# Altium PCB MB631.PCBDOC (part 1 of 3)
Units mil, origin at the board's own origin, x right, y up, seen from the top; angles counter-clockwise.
Board outline 4505 x 6805 mil, 4 copper layers (TopLayer, GND, VCC, BottomLayer); 273 components, 241 nets, 1286 pads, 636 vias.
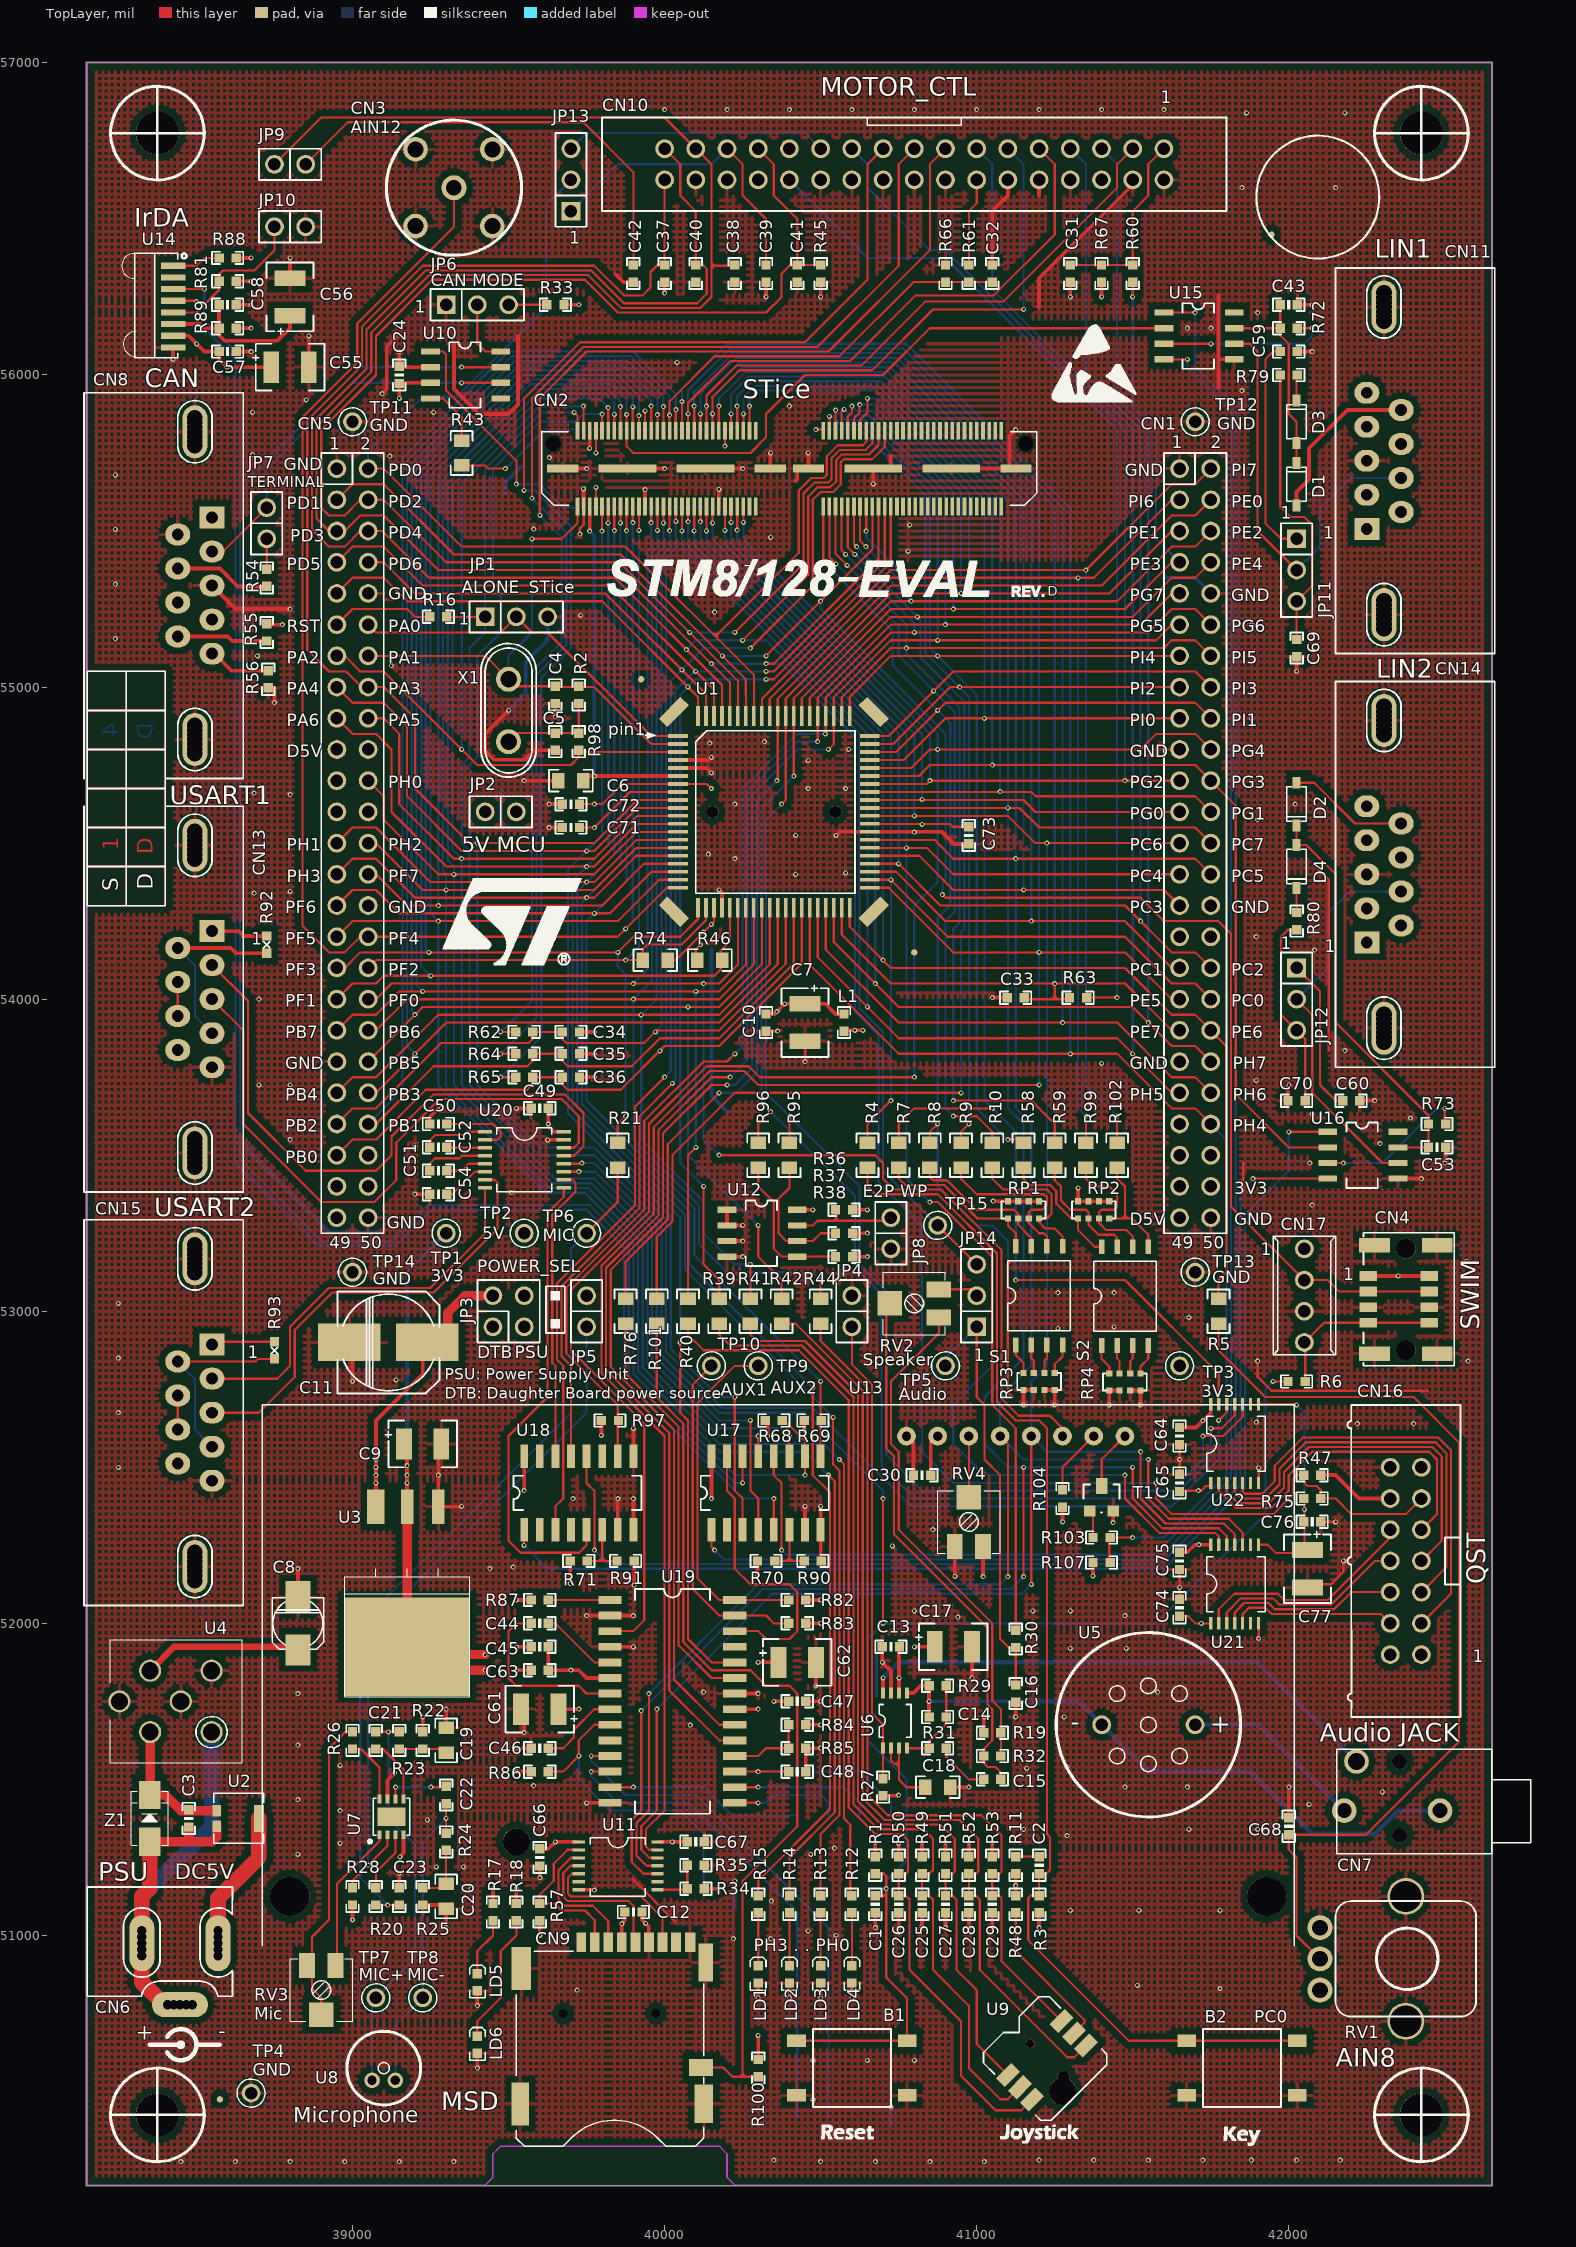
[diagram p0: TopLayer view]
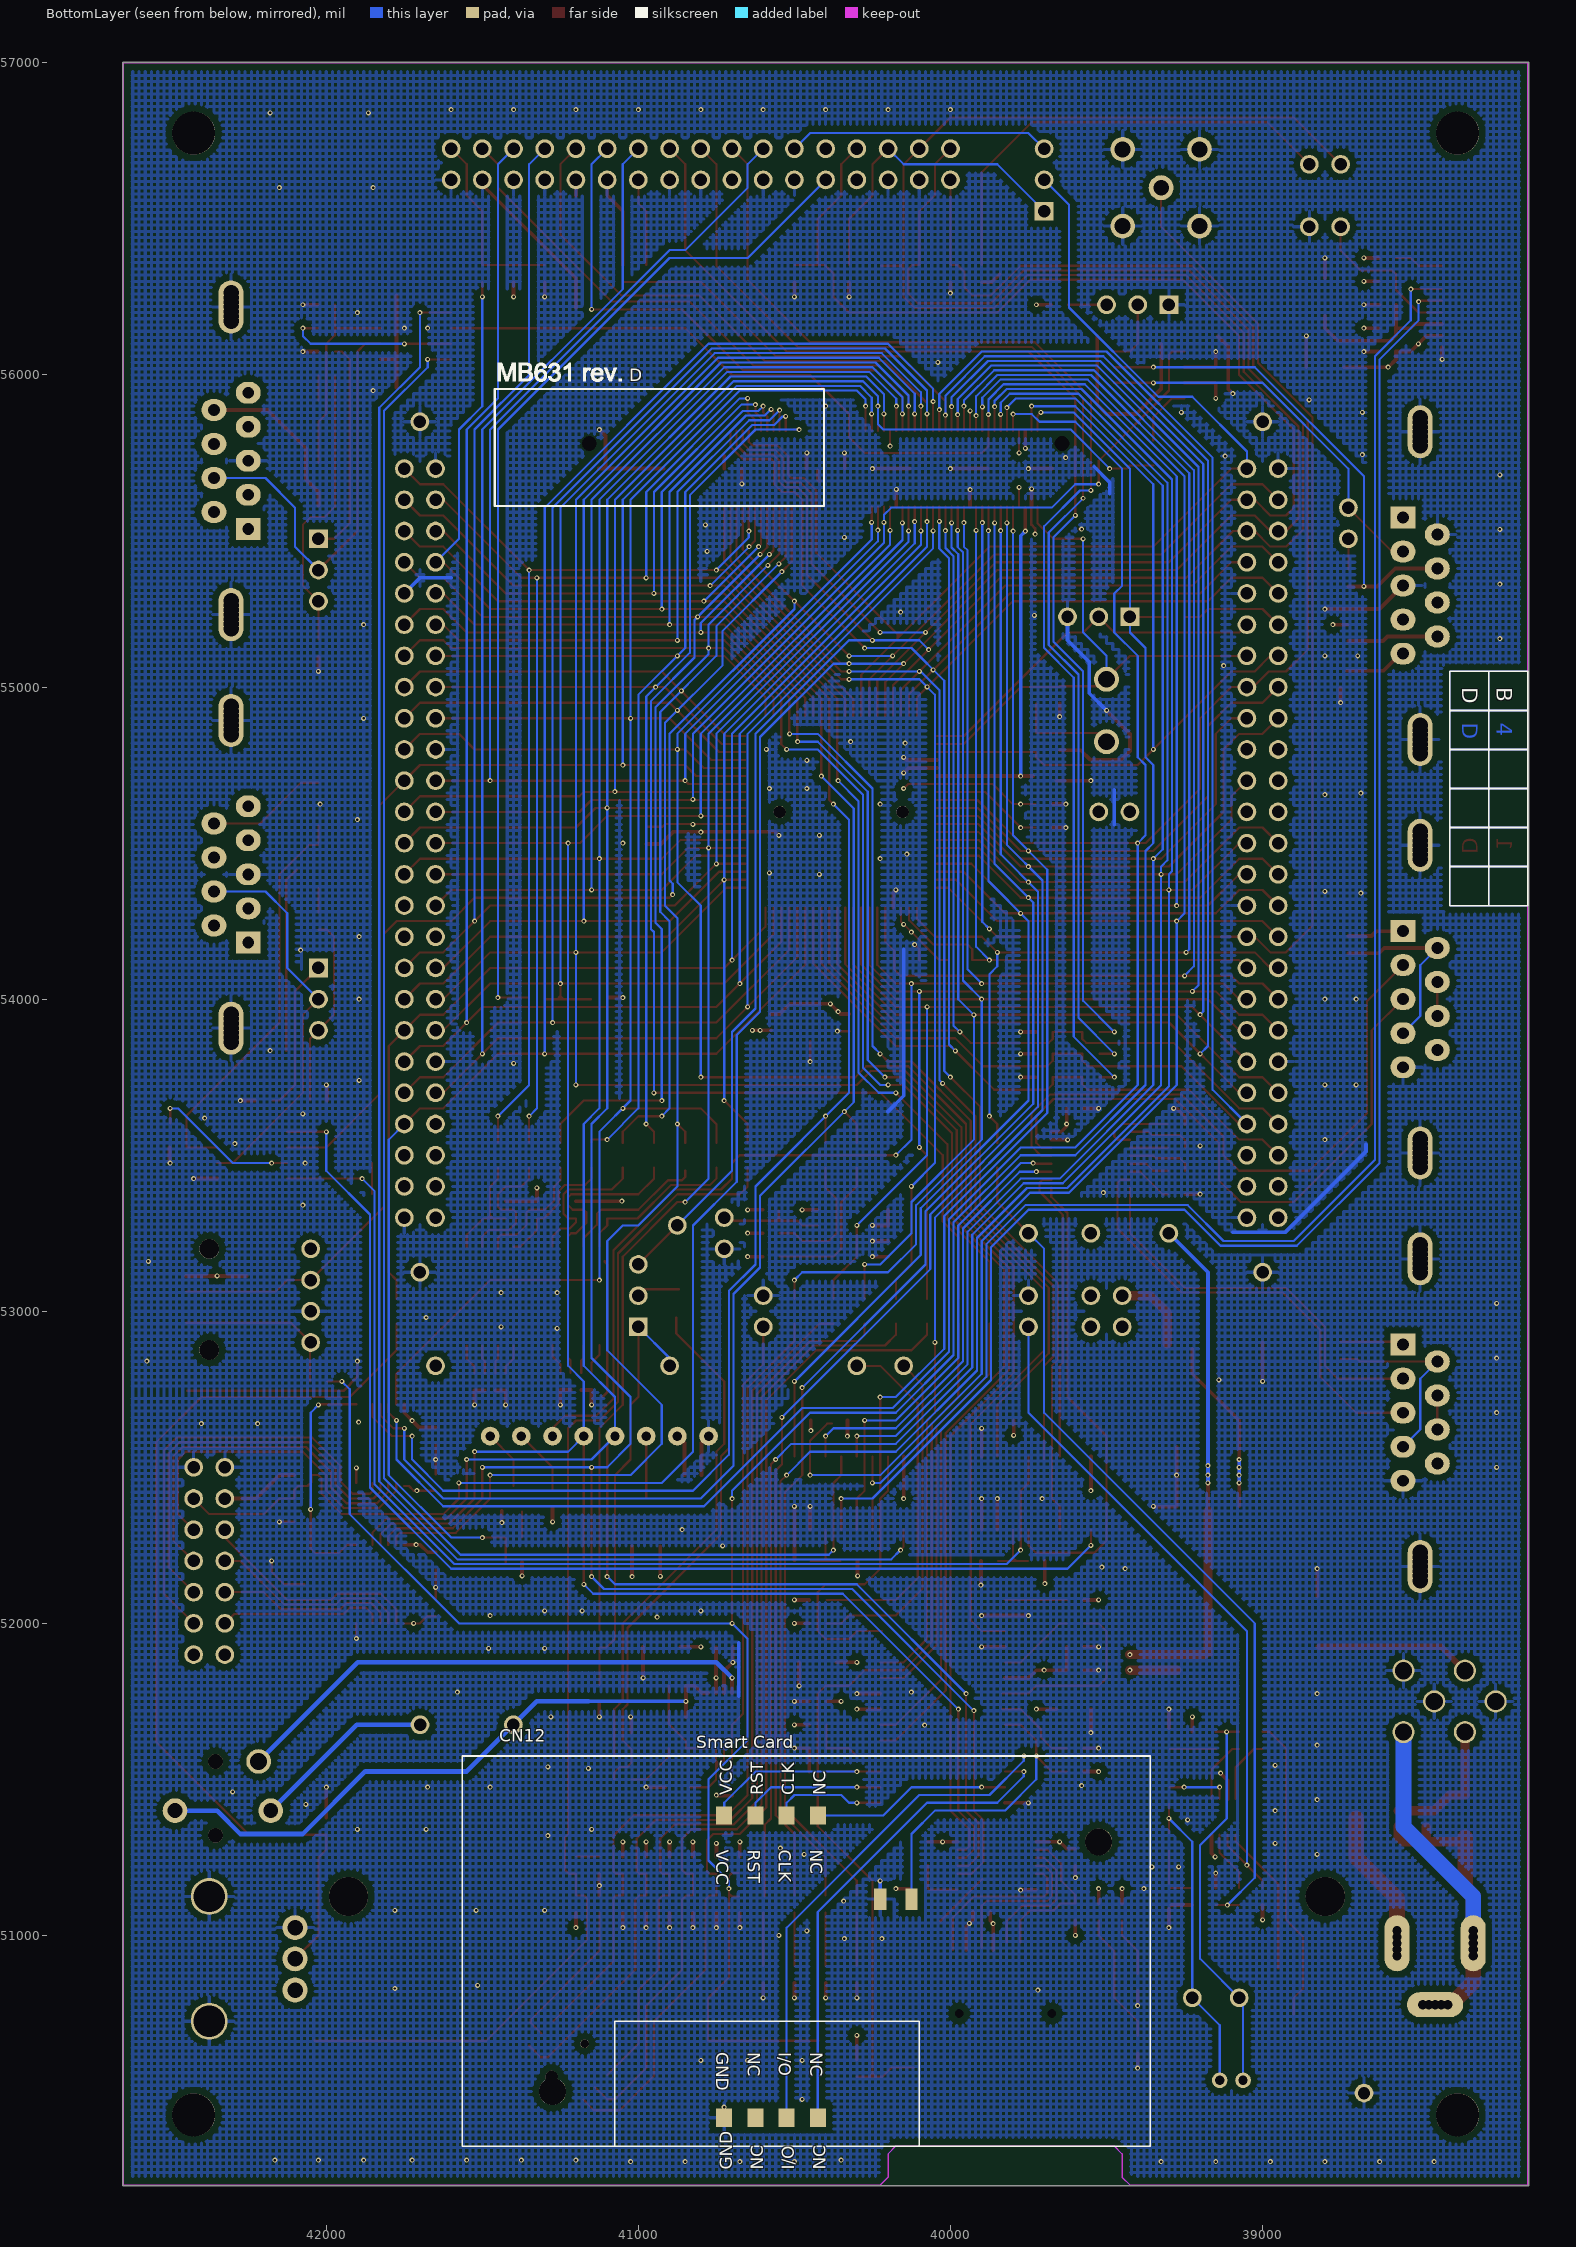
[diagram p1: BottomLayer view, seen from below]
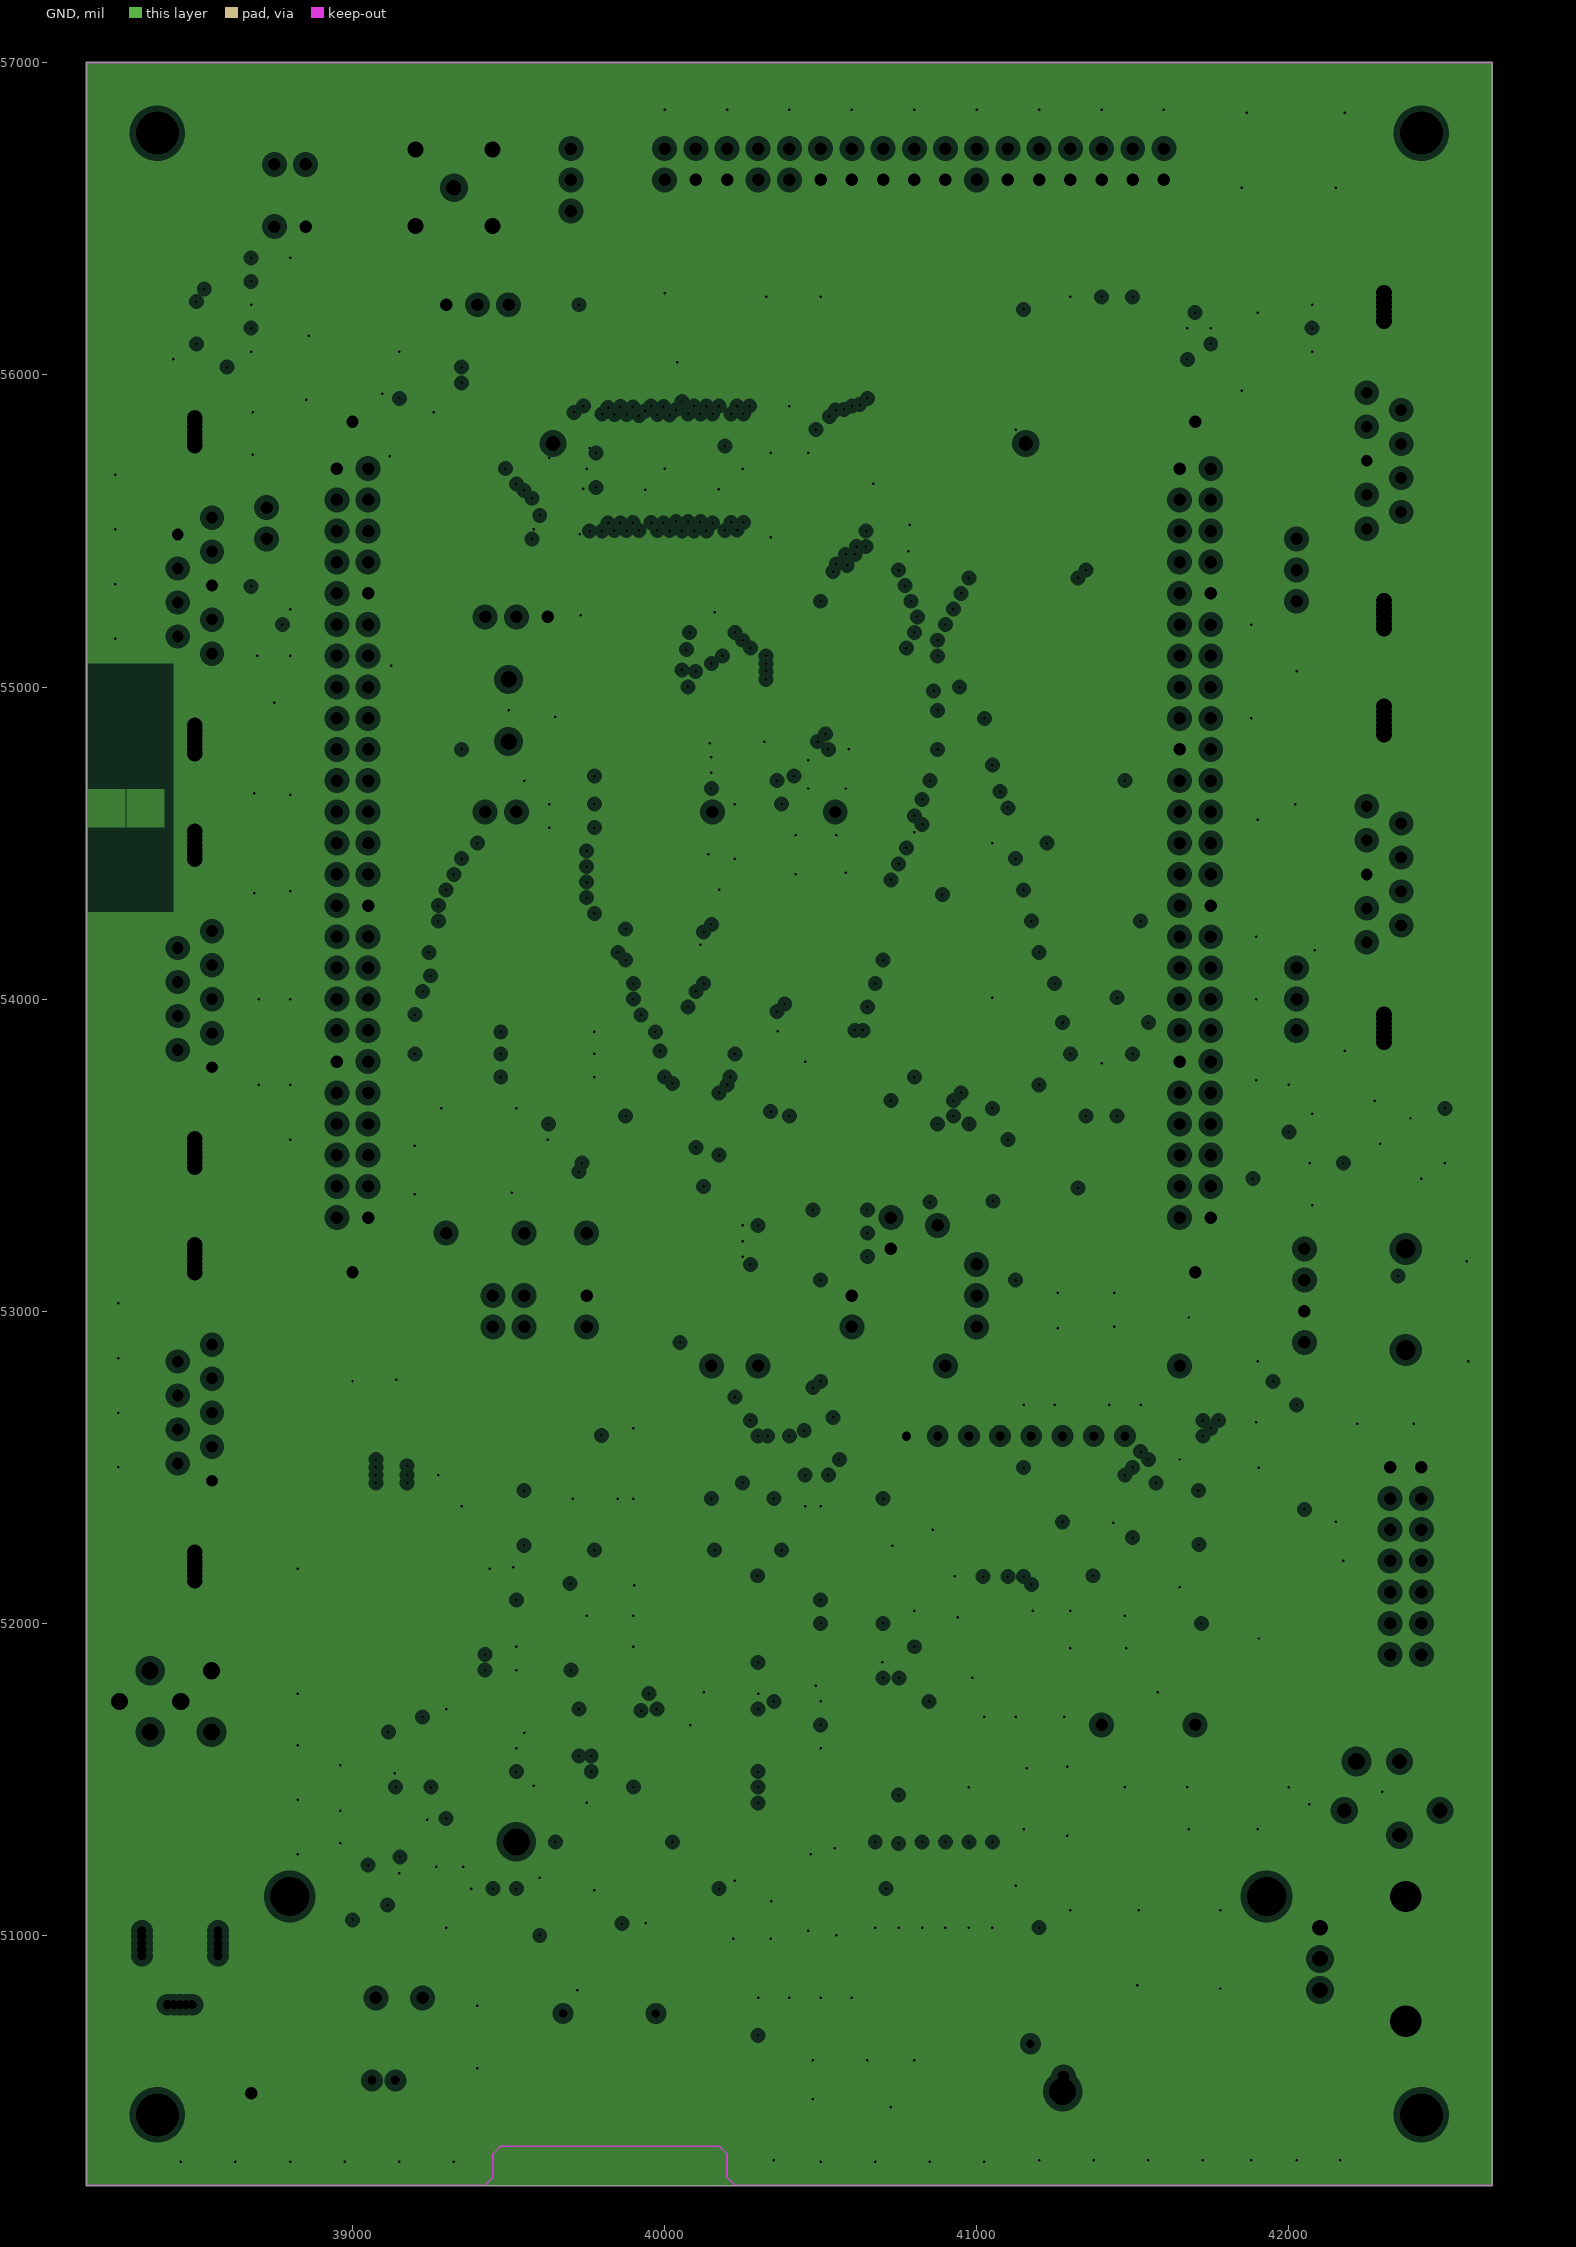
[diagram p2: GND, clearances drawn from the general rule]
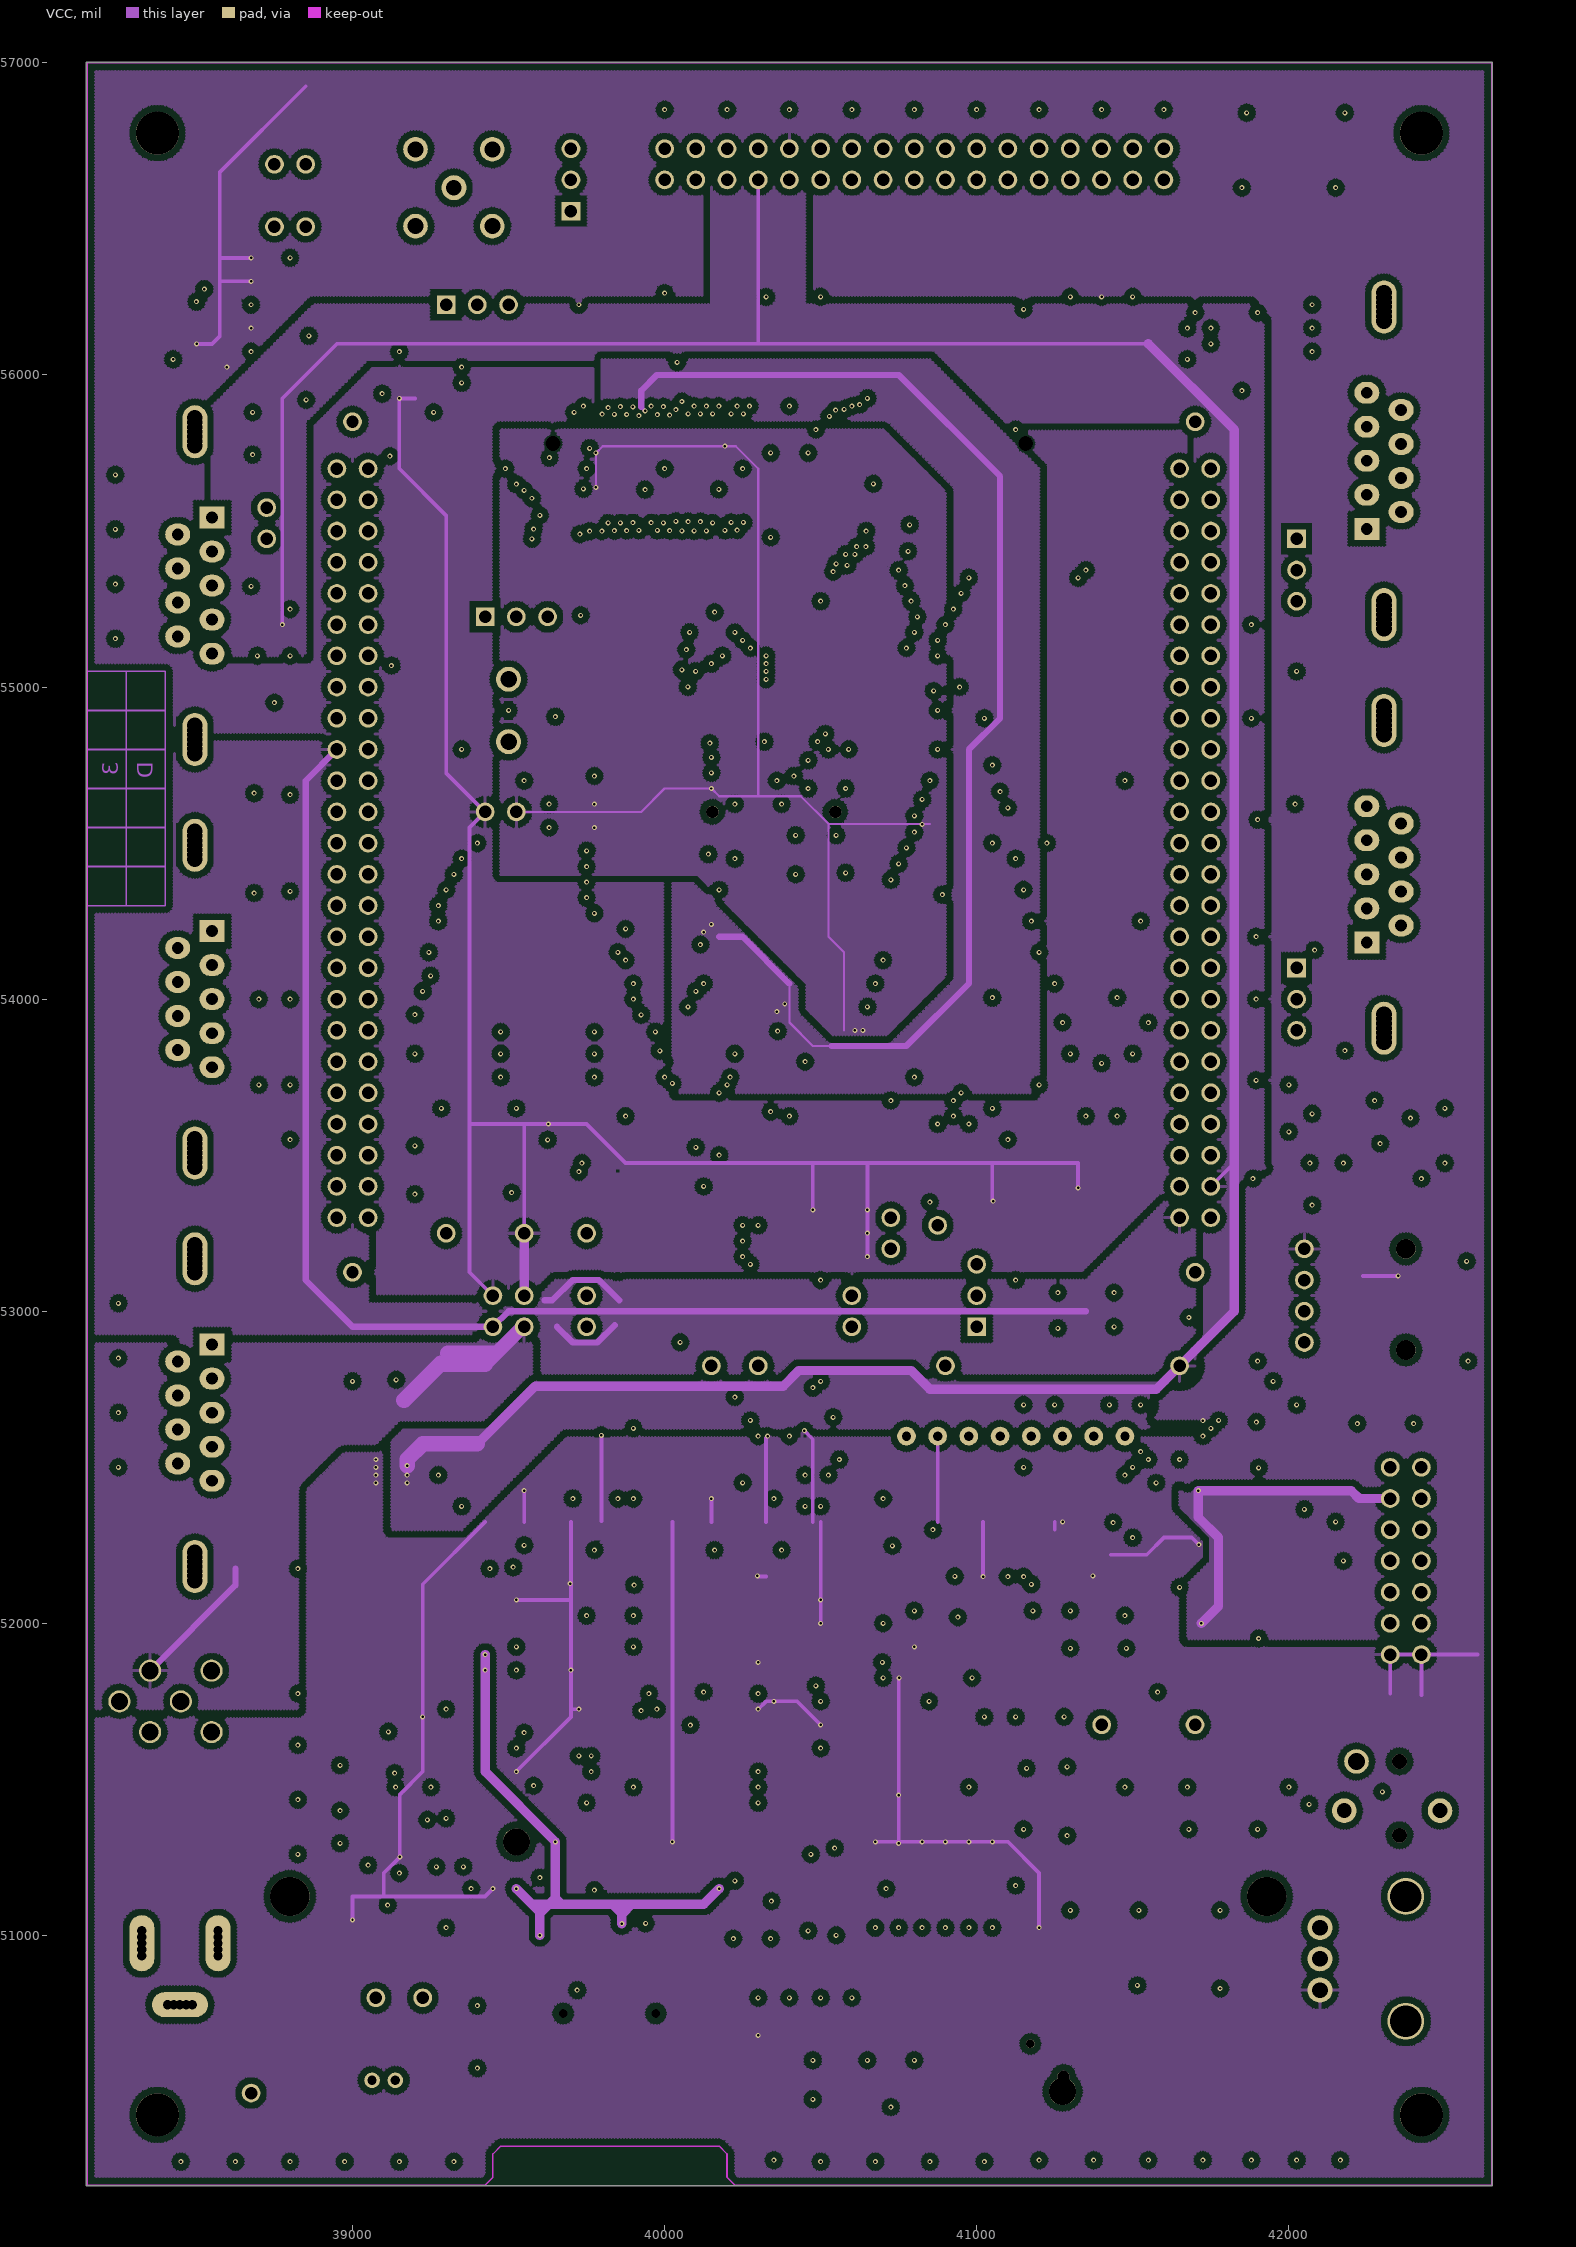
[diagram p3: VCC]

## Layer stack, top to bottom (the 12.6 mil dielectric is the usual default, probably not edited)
TopLayer: signal copper 1.4
Dielectric: core 12.6, FR-4, Dk 4.8
GND: plane copper 1.4, net GND
Dielectric: prepreg 12.6, FR-4, Dk 4.8
VCC: signal copper 1.4
Dielectric: core 12.6, FR-4, Dk 4.8
BottomLayer: signal copper 1.4

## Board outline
38147.5,50197.5 42652.5,50197.5 42652.5,57002.5 38147.5,57002.5

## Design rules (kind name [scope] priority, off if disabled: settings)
Clearance Clearance_2 [InComponent('CN2')] p1: gap=5
Clearance Clearance_1 [(InPoly)] p2: gap=20
Clearance [All] p3: gap=8
ComponentClearance [All] p1 off: gap=10 collisioncheckmode=0
PlaneClearance [All] p1: clearance=20
PlaneConnect [All] p1: planeconnectstyle=Relief reliefexpansion=20 reliefentries=4 reliefconductorwidth=10 reliefairgap=10
PolygonConnect [All] p1: connectstyle=Relief reliefconductorwidth=10 reliefentries=4 polygonreliefangle="90 Angle"
RoutingLayers [All] p1: top layer_v5=TRUE mid layer 1_v5=FALSE bottom layer_v5=TRUE
RoutingVias [All] p1: holewidth=8 width=16 viastyle="Through Hole" minholewidth=5 minwidth=8 maxholewidth=28 maxwidth=50
SolderMaskExpansion [All] p1: expansion=4
TestPointUsage [All] p1: valid=0 allowmultiple=FALSE
Testpoint [All] p1: side=15 testpointundercomponent=TRUE minsize=40 maxsize=100 preferedsize=60 minholesize=20 maxholesize=40 preferedholesize=32 testpointgrid=1 style=1023 order=1234567890
Width Width_3 [InNet('D5V')] p1: maxlimit=300 minlimit=7 preferedwidth=20
Width Width_4 [InNet('E5V')] p2: maxlimit=300 minlimit=7 preferedwidth=50
Width Width_1 [InNet('+3V3')] p3: maxlimit=300 minlimit=7 preferedwidth=30
Width Width_2 [InNet('+5V')] p4: maxlimit=300 minlimit=7 preferedwidth=12
Width Width_7 [InNet('VDD')] p5: maxlimit=300 minlimit=7 preferedwidth=12
Width Width_8 [InNet('VDDA')] p6: maxlimit=300 minlimit=7 preferedwidth=12
Width Width_5 [InNet('GND')] p7: maxlimit=300 minlimit=7 preferedwidth=8
Width Width_6 [InNet('U5V')] p8: maxlimit=300 minlimit=7 preferedwidth=12
Width [All] p9: maxlimit=300 minlimit=5 preferedwidth=7
14 further rules are at their usual default settings.

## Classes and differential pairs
component class JOY_LCD_SDcard_CAN_EEPROM: C24 C25 C26 C27 C28 C29 C30 C66 C67 CN8 CN9 JP6 JP7 JP8 R33 R34 R35 R36 R37 R38 R39 R40 R41 R42 R43 R44 R47 R48 R49 R50 R51 R52 R53 R54 R55 R56 R57 R58 R59 R95 R96 U9 U10 U11 U12 U13
component class UART_LIN_IrDA_SmartCard: B3 B4 C43 C44 C45 C46 C47 C48 C49 C50 C51 C52 C53 C54 C55 C56 C57 C58 C59 C60 C61 C62 C63 CN11 CN12 CN13 CN14 CN15 D1 D2 JP10 JP11 JP12 R68 R69 R70 R71 R72 R73 R76 R78 R79 R80 R81 R82 R83 R84 R85 R86 R87 R88 R89 R90 R91 R92 R93 R94 R97 TP9 TP10 U14 U15 U16 U17 U18 U19 U20
net class PE[0..15]: NetCN13_7 NetR92_1 PE0 PE1 PE2 PE3 PE6 PE7 PE8 PE9 PE10 PE11 PE12 PE13 PE14 PE15 PE[0..15]0 PE[0..15]1 PE[0..15]2 PE[0..15]3 PE[0..15]4 PE[0..15]5 PE[0..15]6 PE[0..15]7 PE[0..15]8 PE[0..15]9 PE[0..15]10 PE[0..15]11 PE[0..15]12 PE[0..15]13 PE[0..15]14 PE[0..15]15
net class PD[0..15]: NetJP13_3 PD0 PD1 PD2 PD3 PD4 PD5 PD6 PD7 PD8 PD9 PD10 PD11 PD12 PD14 PD15 PD[0..15]0 PD[0..15]1 PD[0..15]2 PD[0..15]3 PD[0..15]4 PD[0..15]5 PD[0..15]6 PD[0..15]7 PD[0..15]8 PD[0..15]9 PD[0..15]10 PD[0..15]11 PD[0..15]12 PD[0..15]13 PD[0..15]14 PD[0..15]15
net class PC[0..15]: NetCN12_2 NetCN12_3 NetU19_13 PC3 PC4 PC5 PC6 PC7 PC8 PC9 PC10 PC11 PC12 PC13 PC14 PC15 PC[0..15]0 PC[0..15]1 PC[0..15]2 PC[0..15]3 PC[0..15]4 PC[0..15]5 PC[0..15]6 PC[0..15]7 PC[0..15]8 PC[0..15]9 PC[0..15]10 PC[0..15]11 PC[0..15]12 PC[0..15]13 PC[0..15]14 PC[0..15]15
net class PB[0..15]: PB0 PB1 PB2 PB3 PB4 PB5 PB6 PB7 PB8 PB9 PB10 PB11 PB12 PB13 PB14 PB15 PB[0..15]0 PB[0..15]1 PB[0..15]2 PB[0..15]3 PB[0..15]4 PB[0..15]5 PB[0..15]6 PB[0..15]7 PB[0..15]8 PB[0..15]9 PB[0..15]10 PB[0..15]11 PB[0..15]12 PB[0..15]13 PB[0..15]14 PB[0..15]15
net class PA[0..15]: NetU19_11 NetU19_12 PA0 PA3 PA4 PA5 PA6 PA7 PA8 PA9 PA10 PA11 PA12 PA13 PA14 PA15 PA[0..15]0 PA[0..15]1 PA[0..15]2 PA[0..15]3 PA[0..15]4 PA[0..15]5 PA[0..15]6 PA[0..15]7 PA[0..15]8 PA[0..15]9 PA[0..15]10 PA[0..15]11 PA[0..15]12 PA[0..15]13 PA[0..15]14 PA[0..15]15
component class Extension: CN12 CN13 R59 R60
component class JTAG&SWD: CN7 CN9 CN10 JP10 R101 R102 R103 R104 R105 R109 R110 R111 R122 R124 R125 R129 R130
component class MotorCtrl: C48 C49 C50 C51 C52 C53 C71 C72 C73 C74 C75 C76 CN10 JP8 JP12 R20 R53 R54 R55 R56 R57 R58 R61
component class MCU: B1 BT1 C1 C2 C3 C4 C5 C55 C56 C57 C58 C59 C60 C61 JP9 L1 R1 R2 R15 R26 R83 R84 R86 R87 SW1 SW2 TP8 U1 X1 X2
component class Peripherals: C6 C7 C8 C9 C10 CN1 CN2 CN3 JP1 JP2 JP3 LD1 LD2 LD3 LD4 R3 R4 R5 R6 R7 R8 R9 R11 R12 R13 R14 R16 R17 R18 R19 R20 R21 R63 R65 R66 R67 R68 R69 R80 R88 R89 R90 R91 R112 R113 R114 R116 R118 RV1 T1 T2 TR1 TR2 U2 U3 U4 U5
component class Power: C11 C12 C13 C14 C15 CN4 JP4 LD5 R22 TP1 TP2 TP3 U6 U7 U8 Z1
component class RS232&IrDA: C16 C17 C18 C19 C20 C21 C22 C23 C24 C25 C26 C27 C28 C29 CN5 CN6 JP5 R23 R24 R25 R27 R28 R64 R70 R77 R79 U9 U10 U11
component class Audio: C30 C31 C32 C33 C34 C35 C36 C37 C38 C39 C54 CN8 JP6 JP7 R29 R30 R31 R32 R33 R34 R35 R36 R37 R38 R39 R40 R71 R119 RV2 RV3 TP4 TP5 TP6 TP7 U12 U13 U14 U15
component class LCD&Joystick: B1 B2 B3 C40 C41 C42 C43 C44 C45 C46 C47 C70 R41 R42 R43 R44 R45 R46 R47 R48 R49 R50 R51 R52 R62 R72 R73 R74 R75 R76 R78 R85 R92 R93 R106 R107 R108 R120 R121 U16 U17 U19
component class MC&Extension: C48 C49 C50 C51 C52 C53 C71 C72 C73 C74 C75 CN10 CN12 CN13 JP8 R53 R54 R55 R56 R57 R58 R59 R60 R61
component class SD&SmartCard: C62 C63 C64 C65 C66 C67 C68 C69 CN15 CN16 R81 R82 R94 R95 R96 R97 R98 R99 R100 R115 R117 TP9 TP10 U18
component class Debug: CN7 CN9 CN10 CN11 JP10 R101 R102 R103 R104 R105 R109 R110 R111

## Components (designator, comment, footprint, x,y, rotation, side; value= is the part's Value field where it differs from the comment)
B1 "RESET" PB10 40600,50575 r90 top
B2 "USER" PB10 41850,50575 r90 top
C1 "100nF" 0603P 40675,51100 r90 top
C2 "100nF" 0603P 41200,51225 r270 top
C3 "100nF" 0603P 38475,51375 r270 top
C4 "20pF" 0603 39650,54975 r270 top
C5 "20pF" 0603 39650,54825 r270 top
C6 "470nF" 0805 39700,54700 r270 top
C7 "10uF" TAN-B 40450,53925 r270 top
C8 "10uF" C160M 38825,52000 r270 top
C9 "10uF" TAN-B 39225,52575 r0 top
C10 "10nF" 0603 40325,53925 r270 top
C11 "470uF" C310M 39115,52900 r0 top
C12 "100nF" 0603P 39900,51075 r0 top
C13 "100nF" 0603P 40725,51925 r0 top
C14 "470pF" 0603 40875,51700 r180 top
C15 "150nF" 0603 41050,51500 r180 top
C16 "33nF" 0603 41125,51775 r90 top
C17 "100uF" TAN-B 40925,51925 r0 top
C18 "2.2uF" 0805 40875,51475 r90 top
C19 "2.2uF" 0805 39300,51625 r180 top
C20 "2.2uF" 0805 39300,51125 r0 top
C21 "1uF" 0603 39075,51625 r270 top
C22 "1uF" 0603 39300,51450 r90 top
C23 "do not fit" 0603 39150,51125 r90 top
C24 "100nF" 0603P 39150,56000 r270 top
C25 "100nF" 0603P 40825,51100 r90 top
C26 "100nF" 0603P 40750,51100 r90 top
C27 "100nF" 0603P 40900,51100 r90 top
C28 "100nF" 0603P 40975,51100 r90 top
C29 "100nF" 0603P 41050,51100 r90 top
C30 "100nF" 0603P 40825,52475 r180 top
C31 "1nF" 0603 41300,56325 r90 top
C32 "100nF" 0603 41050,56325 r270 top
C33 "100nF" 0603 41125,54005 r0 top
C34 "do not fit" 0603 39700,53895 r180 top
C35 "do not fit" 0603 39700,53825 r180 top
C36 "do not fit" 0603 39700,53750 r180 top
C37 "do not fit" 0603 40000,56325 r90 top
C38 "do not fit" 0603 40225,56325 r90 top
C39 "do not fit" 0603 40325,56325 r90 top
C40 "do not fit" 0603 40100,56325 r90 top
C41 "do not fit" 0603 40425,56325 r90 top
C42 "10nF" 0603 39900,56325 r90 top
C43 "100nF" 0603P 42000,56225 r0 top
C44 "100nF" 0603P 39600,52000 r0 top
C45 "100nF" 0603P 39600,51925 r180 top
C46 "100nF" 0603P 39600,51600 r180 top
C47 "100nF" 0603P 40425,51750 r0 top
C48 "100nF" 0603P 40425,51525 r180 top
C49 "100nF" 0603P 39600,53650 r180 top
C50 "0.33uF" 0603P 39275,53600 r0 top
C51 "0.33uF" 0603P 39275,53450 r0 top
C52 "0.47uF" 0603P 39275,53525 r0 top
C53 "100nF" 0603P 42475,53525 r0 top
C54 "0.33uF" 0603P 39275,53375 r0 top
C55 "4.7uF" TAN-B 38800,56025 r0 top
C56 "4.7uF" TAN-B 38800,56250 r90 top
C57 "0.1uF" 0603P 38600,56075 r0 top
C58 "0.1uF" 0603P 38600,56225 r0 top
C59 "220pF" 0603 42000,56075 r180 top
C60 "220pF" 0603 42200,53675 r180 top
C61 "47uF" TAN-B 39600,51725 r180 top
C62 "47uF" TAN-B 40425,51875 r0 top
C63 "330nF" 0603 39600,51850 r180 top
C64 "100nF" 0603P 41650,52600 r90 top
C65 "100nF" 0603P 41650,52450 r270 top
C66 "100nF" 0603P 39600,51250 r90 top
C67 "100nF" 0603P 40100,51300 r180 top
C68 "100nF" 0603p 42000,51350 r90 top
C69 "1nF" 0603 42025,55125 r90 top
C70 "1nF" 0603 42025,53675 r0 top
C71 "100nF" 0603P 39700,54550 r180 top
C72 "100nF" 0603P 39700,54625 r180 top
C73 "100nF" 0603P 40975,54525 r270 top
C74 "100nF" 0603P 41650,52050 r270 top
C75 "100nF" 0603P 41650,52200 r90 top
C76 "100nF" 0603P 42075,52325 r180 top
C77 "10uF(do not fit)" TAN-B 42060,52175 r270 top
CN1 "Header 25X2 on the left" 2*25P 41650,55700 r0 top locked
CN2 "QTH-060-01-L-D-A" QTH-060-01-L-D-A 40400,55700 r0 top
CN3 "VB334" VB334 39325,56600 r0 top
CN4 "214017" SMD214012 42375,53200 r270 top
CN5 "Header 25X2 on the right" 2*25P 38950,55700 r0 top locked
CN6 "DC-10B" DC10B 38325,50975 r0 top
CN7 "ST-613" PJST-613 42650,51400 r180 top
CN8 "DB9-male CAN connector" DB9/M 38550,55325 r90 top
CN9 "PJS008-2000" MSD(PJS008) 39675,50750 r270 top
CN10 "MC_connector" IDC34S 41600,56725 r270 top locked
CN11 "DB9-male LIN1" DB9/M 42250,55725 r270 top
CN12 "C816" SAM(C816) 40400,50900 r270 bottom
CN13 "DB9-male USART1" DB9/M 38550,54000 r90 top
CN14 "DB9-male LIN2" DB9/M 42250,54400 r270 top
CN15 "DB9-male USART2" DB9/M 38550,52675 r90 top
CN16 "QST(HE10x14)" IDC14S 42425,51900 r180 top
CN17 "609-1306-ND(do not fit)" 609-1306-ND 42050,53200 r270 top
D1 "BAT48ZFILM" SOD-123 42025,55650 r90 top
D2 "BAT48ZFILM" SOD-123 42025,54625 r270 top
D3 "BAT48ZFILM" SOD-123 42025,55850 r90 top
D4 "BAT48ZFILM" SOD-123 42025,54425 r270 top
JP1 "" SIP3 39425,55225 r0 top
JP2 "" SIP2 39525,54600 r180 top
JP3 "Header 2X2H" 2*2P 39450,52950 r0 top
JP4 "" SIP2 40600,52950 r90 top
JP5 "" SIP2 39750,52950 r90 top
JP6 "" SIP3 39300,56225 r0 top
JP7 "" SIP2 38725,55475 r90 top
JP8 "" SIP2 40725,53300 r270 top
JP9 "" SIP2 38750,56675 r0 top
JP10 "" SIP2 38750,56475 r0 top
JP11 "" SIP3 42025,55475 r270 top
JP12 "" SIP3 42025,54100 r270 top
JP13 "" SIP3 39700,56525 r90 top
JP14 "" SIP3 41000,52950 r90 top
L1 "BEAD" 0603 40575,53925 r90 top
LD1 "red" D0603 40300,50875 r0 top
LD2 "red" D0603 40400,50875 r0 top
LD3 "red" D0603 40500,50875 r0 top
LD4 "red" D0603 40600,50875 r0 top
LD5 "red" D0603 39400,50850 r0 top
LD6 "red" D0603 39400,50650 r0 top
R1 "10K" 0603 40675,51225 r90 top
R2 "1M" 0603 39725,54975 r90 top
R3 "4K7" 0603 41200,51100 r270 top
R4 "0" 0805 40650,53500 r0 top
R5 "0" 0805 41775,53000 r0 top
R6 "0" 0603 42025,52775 r0 top
R7 "0" 0805 40750,53500 r180 top
R8 "0" 0805 40850,53500 r180 top
R9 "0" 0805 40950,53500 r180 top
R10 "0" 0805 41050,53500 r180 top
R11 "100" 0603 41125,51225 r90 top
R12 "1K" 0603 40600,51100 r90 top
R13 "1K" 0603 40500,51100 r90 top
R14 "1K" 0603 40400,51100 r90 top
R15 "1K" 0603 40300,51100 r90 top
R16 "820" 0603 39275,55225 r0 top
R17 "300" 0603 39450,51075 r90 top
R18 "300" 0603 39525,51075 r90 top
R19 "0" 0603 41050,51650 r0 top
R20 "0" 0603 39075,51125 r90 top
R21 "0" 0805 39850,53500 r0 top
R22 "1K" 0603 39225,51625 r90 top
R23 "1K" 0603 39150,51625 r90 top
R24 "1K" 0603 39300,51300 r90 top
R25 "1K" 0603 39225,51125 r90 top
R26 "1K" 0603 39000,51625 r270 top
R27 "10K" 0603 40700,51475 r270 top
R28 "10K" 0603 39000,51125 r90 top
R29 "100K" 0603 40875,51800 r180 top
R30 "1.2K" 0603 41125,51950 r270 top
R31 "22K" 0603 40875,51600 r180 top
R32 "0(don't solder)" 0603 41050,51575 r180 top
R33 "10K" 0603 39650,56225 r0 top
R34 "0" 0603 40100,51150 r0 top
R35 "do not fit" 0603 40100,51225 r180 top
R36 "10K" 0603 40575,53325 r180 top
R37 "4K7" 0603 40575,53250 r180 top
R38 "4K7" 0603 40575,53175 r180 top
R39 "0" 0805 40175,53000 r180 top
R40 "0" 0805 40075,53000 r180 top
R41 "0" 0805 40275,53000 r180 top
R42 "0" 0805 40375,53000 r180 top
R43 "0" 0805 39350,55750 r0 top
R44 "0" 0805 40500,53000 r180 top
R45 "10K" 0603 40500,56325 r90 top
R46 "0" 0805 40145,54125 r90 top
R47 "do not fit" 0603 42075,52475 r0 top
R48 "100" 0603 41125,51100 r270 top
R49 "10K" 0603 40825,51225 r270 top
R50 "10K" 0603 40750,51225 r90 top
R51 "10K" 0603 40900,51225 r90 top
R52 "10K" 0603 40975,51225 r90 top
R53 "10K" 0603 41050,51225 r90 top
R54 "120" 0603 38725,55350 r90 top
R55 "do not fit" 0603 38725,55175 r270 top
R56 "0" 0603 38730,55025 r90 top
R57 "4K7" 0603 39600,51075 r270 top
R58 "0" 0805 41150,53500 r180 top
R59 "0" 0805 41250,53500 r180 top
R60 "0" 0603 41500,56325 r270 top
R61 "0" 0603 40975,56325 r270 top
R62 "0" 0603 39550,53895 r180 top
R63 "0" 0603 41325,54005 r180 top
R64 "0" 0603 39550,53825 r180 top
R65 "0" 0603 39550,53750 r180 top
R66 "100K" 0603 40900,56325 r270 top
R67 "3.3K" 0603 41400,56325 r270 top
R68 "10K" 0603 40350,52650 r0 top
R69 "10K" 0603 40475,52650 r0 top
R70 "10K" 0603 40325,52200 r0 top
R71 "10K" 0603 39725,52200 r0 top
R72 "4K7" 0603 42000,56150 r180 top
R73 "4K7" 0603 42475,53600 r180 top
R74 "0" 0805 39970,54125 r90 top
R75 "50K" 0603 42075,52400 r0 top
R76 "0" 0805 39875,53000 r0 top
R79 "1K" 0603 42000,56000 r180 top
R80 "1K" 0603 42025,54250 r270 top
R81 "10K" 0603 38600,56300 r0 top
R82 "10K" 0603 40425,52075 r180 top
R83 "10K" 0603 40425,52000 r180 top
R84 "10K" 0603 40425,51675 r180 top
R85 "10K" 0603 40425,51600 r0 top
R86 "100K" 0603 39600,51525 r0 top
R87 "4K7" 0603 39600,52075 r0 top
R88 "5" 0603 38600,56375 r180 top
R89 "47" 0603 38600,56150 r180 top
R90 "0" 0603 40475,52200 r0 top
R91 "0" 0603 39875,52200 r180 top
R92 "do not fit" 0603_NC 38725,54175 r90 top
R93 "do not fit" 0603_NC 38750,52875 r90 top
R95 "0" 0805 40400,53500 r0 top
R96 "0" 0805 40300,53500 r0 top
R97 "10K" 0603 39825,52650 r0 top
R98 "60" 0603 39725,54825 r90 top
R99 "0" 0805 41350,53500 r180 top
R100 "10K" 0603 40300,50575 r90 top
R101 "0" 0805 39975,53000 r180 top
R102 "0" 0805 41450,53500 r180 top
R103 "1K" 0603 41400,52275 r0 top
R104 "0" 0603 41275,52400 r90 top
R107 "do not fit" 0603 41400,52195 r0 top
RP1 "10K" RES-4B 41150,53325 r0 top
RP2 "10K" RES-4B 41375,53325 r0 top
RP3 "50" RES-4B 41200,52775 r0 top
RP4 "50" RES-4B 41475,52773.27 r0 top
RV1 "10K" ADJRH 42100,50925 r270 top
RV2 "50K" 3314-J 40800,53025 r270 top
RV3 "20K" 3314-J 38900,50825 r0 top
RV4 "50K(do not fit)" 3314-J 40975,52325 r180 top
S1 "SW" GWL4 41200,53050 r90 top
S2 "SW" GWL4 41475,53048.27 r90 top
T1 "9013" SOT-23 41400,52400 r0 top
TP1 "3V3" TP 39300,53250 r0 top
TP2 "+5V" TP 39550,53250 r270 top
TP3 "+3V3" TP 41650,52825 r270 top
TP4 "Ground" TP 38675,50495 r270 top
TP5 "Audio" TP 40900,52825 r90 top
TP6 "MIC_OUT" TP 39750,53250 r0 top
TP7 "MIC+" TP 39075,50800 r0 top
TP8 "MIC-" TP 39225,50800 r0 top
TP9 "AUX2" TP 40300,52825 r0 top
TP10 "AUX1" TP 40150,52825 r0 top
TP11 "GND" TP 39000,55850 r0 top
TP12 "GND" TP 41700,55850 r0 top
TP13 "GND" TP 41700,53125 r0 top
TP14 "GND" TP 39000,53125 r0 top
TP15 "BEEP" TP 40875,53275 r0 top
U1 "STM8S2XX" LQFP80 40350,54600 r0 top
U2 "ZEN056V130A24LS" polyzen 38700,51375 r180 top
U3 "LD1086D2M33" D2PAK/A 39175,51925 r90 top
U4 "BNX002-01" BNX001 38450,51750 r180 top
U5 "KDMG15008-03" KS1508 41550,51675 r180 top
U6 "TS4871IST" TSSOP8 40700,51600 r90 top
U7 "MAX4061ETA+T" QFNT8 39125,51380 r90 top
U8 "KECG2740TBL" KEC2740 39100,50575 r90 top
U9 "MT008-A" JOY 41225,50600 r45 top
U10 "L9616D" SO8 39250,56075 r270 top
U11 "MAX3378EEUD" TSSOP14 39725,51300 r0 top
U12 "M24C64-WMN6" SO8 40200,53325 r270 top
U13 "HXM122032-GB1 (5V)" LCD12232-GB1 40775,52600 r0 top locked
U14 "TFDU4300" IR_VISHAY3 38425,56350 r180 top
U15 "L9638D" SO8 41600,56200 r270 top
U16 "L9638D" SO8 42125,53575 r270 top
U17 "M74HC4052M1R" SO16 40150,52300 r0 top
U18 "M74HC4052M1R" SO16 39550,52300 r0 top
U19 "ST8024CDR" SO28 39825,52075 r0 top
U20 "ST3232ECTR" TSSOP16 39425,53575 r0 top
U21 "MAX3378EEUD" TSSOP14 41750,52000 r90 top
U22 "MAX3378EEUD" TSSOP14 41750,52450 r90 top
X1 "24MHz (with socket)" XTAL_socket 39500,54925 r270 top
Z1 "SMAJ5.0A-TR" 1R1C 38350,51375 r0 top

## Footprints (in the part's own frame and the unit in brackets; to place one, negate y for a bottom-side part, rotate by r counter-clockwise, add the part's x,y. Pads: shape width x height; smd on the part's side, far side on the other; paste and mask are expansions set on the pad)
1R1C [mm]
  rect 1.75x2.3 smd: 1(0,-1.9) 2(0,1.9)
  silkscreen extent -1.5,-2.2 1.5,2.2
2*2P [mil]
  round 60 hole 40: 1(0,0) 2(0,100) 3(100,0) 4(100,100)
  silkscreen extent -50,-50 150,150
2*25P [mil]
  round 60 hole 40: 1(0,0) 2(100,0) 3(0,-100) 4(100,-100) 5(0,-200) 6(100,-200) 7(0,-300) 8(100,-300) 9(0,-400) 10(100,-400) 11(0,-500) 12(100,-500) 13(0,-600) 14(100,-600) 15(0,-700) 16(100,-700) 17(0,-800) 18(100,-800) 19(0,-900) 20(100,-900) 21(0,-1000) 22(100,-1000) 23(0,-1100) 24(100,-1100) 25(0,-1200) 26(100,-1200) 27(0,-1300) 28(100,-1300) 29(0,-1400) 30(100,-1400) 31(0,-1500) 32(100,-1500) 33(0,-1600) 34(100,-1600) 35(0,-1700) 36(100,-1700) 37(0,-1800) 38(100,-1800) 39(0,-1900) 40(100,-1900) 41(0,-2000) 42(100,-2000) 43(0,-2100) 44(100,-2100) 45(0,-2200) 46(100,-2200) 47(0,-2300) 48(100,-2300) 49(0,-2400) 50(100,-2400)
  silkscreen extent -50,-2450 150,50
0603 [mil]
  rect 30x30 smd: 1(-27.5,0) 2(27.5,0)
  silkscreen extent -50,-20 50,20
0603_NC [mil]
  rect 30x30 smd: 1(-27.5,0) 2(27.5,0)
  silkscreen extent -11,-10 9,10
0603P [mil]
  rect 30x30 smd: 1(-27.5,0) 2(27.5,0)
  silkscreen extent -50,-20 50,20
0603p [mil]
  rect 30x30 smd: 1(-27.5,0) 2(27.5,0)
  silkscreen extent -50,-20 50,20
609-1306-ND [mil]
  round 60 hole 40: 1(0,0) 2(100,0) 3(200,0) 4(300,0)
  silkscreen extent -40,-100 340,100
0805 [mil]
  rect 50x40 smd: 1(0,40) 2(0,-40)
  silkscreen extent -35,-70 35,70
3314-J [mm]
  rect 1.3x2 smd: 1(-1.15,2) 3(1.15,2)
  rect 2x2 smd: 2(0,-2)
  silkscreen extent -2.54,-2.54 2.54,2.54
ADJRH [mil]
  round 118.11 hole 100: 0(-200,275) 0(200,275)
  round 80 hole 50: 1(-100,0) 2(0,0) 3(100,0)
  silkscreen extent -185,50 185,500
BNX001 [mm]
  round 1.8 hole 1.4: 1(2.5,2.5) 2(-2.5,2.5) 3(2.5,-2.5) 4(0,0) 5(5,0) 6(-2.5,-2.5)
  silkscreen extent -5,-5 5.76,5
C160M [mil]
  rect 100x80 smd paste-23.62 mask-23.62: 1(85,0) 2(-85,0)
  silkscreen extent -83,-83 83,83
C310M [mil]
  rect 200x120 smd paste-39.37 mask-39.37: 1(125,0) 2(-125,0)
  silkscreen extent -163,-163 163,163
D2PAK/A [mm]
  rect 2.8x1 smd: 1(11.4,-2.54) 2(11.4,0)
  rect 8x10.2 smd: 2(0,0)
  rect 2.8x1.42 smd: 3(11.4,2.54)
  silkscreen extent -4.06,-5.08 6.35,5.08
D0603 [mil]
  rect 30x30 smd: 1(0,27.5) 2(0,-27.5)
  silkscreen extent -25,-50 25,55
DB9/M [mil]
  round 50 hole 50: 0(-538,55) 0(-523,55) 0(-508,55) 0(-493,55) 0(-478,55) 0(-463,55) 0(-448,55) 0(448,55) 0(463,55) 0(478,55) 0(493,55) 0(508,55) 0(523,55) 0(538,55)
  oval 170x80 hole 50: 0(-493,55) 0(493,55)
  rect 70x80 hole 38: 1(218,0)
  oval 70x80 hole 38: 2(109,0) 3(0,0) 4(-109,0) 5(-218,0) 6(164,110) 7(55,110) 8(-54,110) 9(-163,110)
  silkscreen extent -618,-100 618,410
DC10B [mil]
  round 45 hole 30: 1(244.09,-40) 1(244.09,-20) 1(244.09,20) 1(244.09,40) 2(82.05,-196.85) 2(102.05,-196.85) 2(142.05,-196.85) 2(162.05,-196.85) 3(0,-40) 3(0,-20) 3(0,20) 3(0,40)
  oval 80x180 hole 30: 1(244.1,0) 3(0,0)
  oval 180x80 hole 30: 2(122.05,-196.85)
  silkscreen extent -175,-170 290,180
GWL4 [mm]
  rect 1.2x0.45 smd: 1(-4.02,1.905) 2(4.02,1.905) 3(-4.02,0.635) 4(4.02,0.635) 5(-4.02,-0.635) 6(4.02,-0.635) 7(-4.02,-1.905) 8(4.02,-1.905)
  silkscreen extent -2.86,-2.54 2.86,2.54
IDC14S [mil]
  round 60 hole 40: 1(0,0) 2(100,0) 3(0,-100) 4(100,-100) 5(0,-200) 6(100,-200) 7(0,-300) 8(100,-300) 9(0,-400) 10(100,-400) 11(0,-500) 12(100,-500) 13(0,-600) 14(100,-600)
  silkscreen extent -125,-800 237,200
IDC34S [mil]
  round 60 hole 40: 1(0,0) 2(100,0) 3(0,-100) 4(100,-100) 5(0,-200) 6(100,-200) 7(0,-300) 8(100,-300) 9(0,-400) 10(100,-400) 11(0,-500) 12(100,-500) 13(0,-600) 14(100,-600) 15(0,-700) 16(100,-700) 17(0,-800) 18(100,-800) 19(0,-900) 20(100,-900) 21(0,-1000) 22(100,-1000) 23(0,-1100) 24(100,-1100) 25(0,-1200) 26(100,-1200) 27(0,-1300) 28(100,-1300) 29(0,-1400) 30(100,-1400) 31(0,-1500) 32(100,-1500) 33(0,-1600) 34(100,-1600)
  silkscreen extent -100,-1800 200,200
IR_VISHAY3 [mm]
  rect 2x0.5 smd: 1(0,0) 2(0,0.95) 3(0,1.9) 4(0,2.85) 5(0,3.8) 6(0,4.75) 7(0,5.7) 8(0,6.65)
  silkscreen extent -1.1,-1 4.17,7.5
JOY [mm]
  round 1 hole 1 unplated: 0(0,-1.9)
  round 0.7 hole 0.7 unplated: 0(0,1.9)
  rect 1.778x1.016 smd: 1(-3.1,1.4) 2(-3.1,0) 3(-3.1,-1.4) 4(3.1,-1.4) 5(3.1,0) 6(3.1,1.4)
  silkscreen extent -3.8,-3.7 3.8,4.1
KEC2740 [mm]
  round 1.27 hole 0.762: 1(-1,-0.95) 2(-1,0.95)
  silkscreen extent -3,-3 3,3
KS1508 [mil]
  round 60 hole 40: 1(-149.61,0) 2(149.61,0)
  silkscreen extent -295,-295 295,295
LCD12232-GB1 [mil]
  round 125.98 hole 125.98 unplated: 0(-1975.98,-1475) 0(1153.94,-1475)
  round 60 hole 30: 1(0,0) 2(100,0) 3(200,0) 4(300,0) 5(400,0) 6(500,0) 7(600,0) 8(700,0)
  silkscreen extent -2065,-1632 1243,100
LQFP80 [mm]
  rect 1x2.5 smd rot 45: 0(-8.13,-8.13) 0(8.13,8.13)
  rect 1x2.5 smd rot 135: 0(-8.13,8.13) 0(8.13,-8.13)
  round 1 hole 1 unplated: 0(-5,0) 0(5,0)
  rect 1.6x0.3 smd: 1(-7.8,6.175) 2(-7.8,5.525) 3(-7.8,4.875) 4(-7.8,4.225) 5(-7.8,3.575) 6(-7.8,2.925) 7(-7.8,2.275) 8(-7.8,1.625) 9(-7.8,0.975) 10(-7.8,0.325) 11(-7.8,-0.325) 12(-7.8,-0.975) 13(-7.8,-1.625) 14(-7.8,-2.275) 15(-7.8,-2.925) 16(-7.8,-3.575) 17(-7.8,-4.225) 18(-7.8,-4.875) 19(-7.8,-5.525) 20(-7.8,-6.175) 41(7.8,-6.175) 42(7.8,-5.525) 43(7.8,-4.875) 44(7.8,-4.225) 45(7.8,-3.575) 46(7.8,-2.925) 47(7.8,-2.275) 48(7.8,-1.625) 49(7.8,-0.975) 50(7.8,-0.325) 51(7.8,0.325) 52(7.8,0.975) 53(7.8,1.625) 54(7.8,2.275) 55(7.8,2.925) 56(7.8,3.575) 57(7.8,4.225) 58(7.8,4.875) 59(7.8,5.525) 60(7.8,6.175)
  rect 0.3x1.6 smd: 21(-6.175,-7.8) 22(-5.525,-7.8) 23(-4.875,-7.8) 24(-4.225,-7.8) 25(-3.575,-7.8) 26(-2.925,-7.8) 27(-2.275,-7.8) 28(-1.625,-7.8) 29(-0.975,-7.8) 30(-0.325,-7.8) 31(0.325,-7.8) 32(0.975,-7.8) 33(1.625,-7.8) 34(2.275,-7.8) 35(2.925,-7.8) 36(3.575,-7.8) 37(4.225,-7.8) 38(4.875,-7.8) 39(5.525,-7.8) 40(6.175,-7.8) 61(6.175,7.8) 62(5.525,7.8) 63(4.875,7.8) 64(4.225,7.8) 65(3.575,7.8) 66(2.925,7.8) 67(2.275,7.8) 68(1.625,7.8) 69(0.975,7.8) 70(0.325,7.8) 71(-0.325,7.8) 72(-0.975,7.8) 73(-1.625,7.8) 74(-2.275,7.8) 75(-2.925,7.8) 76(-3.575,7.8) 77(-4.225,7.8) 78(-4.875,7.8) 79(-5.525,7.8) 80(-6.175,7.8)
MSD(PJS008) [mm]
  round 0.6 hole 0.7: 0(0,7.55) 0(0,0)
  rect 1.6x0.8 smd: 1(-5.8,1.475) 2(-5.8,2.575) 3(-5.8,3.675) 4(-5.8,4.775) 5(-5.8,5.875) 6(-5.8,6.975) 7(-5.8,8.075) 8(-5.8,9.175)
  rect 1.6x0.85 smd: 9(-5.8,10.325)
  rect 1.4x1.95 smd: 10(4.4,11.225)
  rect 3.5x1.6 smd: G1(-3.65,-3.4)
  rect 3.1x1.5 smd: G2(7.35,11.45)
  rect 3.5x1.4 smd: G3(7.35,-3.5)
  rect 3.1x1.2 smd: G4(-4.15,11.6)
  silkscreen extent -5.07,-3.81 10.8,11.43
PB10 [mil]
  rect 40x60 smd: 1(-87.5,177.17) 2(87.5,177.17) 3(87.5,-177.17) 4(-87.5,-177.17)
  silkscreen extent -125,-125 125,125
PJST-613 [mm]
  round 2 hole 1.2: 1(4.2,0) 10(12,0)
  round 2 hole 1.4: 2(11,-4)
  round 1.2 hole 1.2 unplated: G1(7.5,2) G2(7.5,-4)
  silkscreen extent -3.2,-5 12.6,3.5
polyzen [mm]
  rect 0.8x2.21 smd: 1(0,0)
  rect 0.7x0.94 smd: 2(3.429,0.635) 3(3.429,-0.635)
  silkscreen extent -0.38,-2.03 3.68,2.03
QFNT8 [mm]
  rect 0.7x0.3 smd: 1(-1.45,0.975) 2(-1.45,0.325) 3(-1.45,-0.325) 4(-1.45,-0.975) 5(1.45,-0.975) 6(1.45,-0.325) 7(1.45,0.325) 8(1.45,0.975)
  rect 1.5x2.3 smd: ""(0,0)
  silkscreen extent -2.13,-1.5 1.5,1.88
QTH-060-01-L-D-A [mm]
  round 1 hole 1.2 unplated: 0(-19.24,2.035) 0(19.24,2.035)
  rect 0.3x1.45 smd: 1(-17.25,3.085) 2(-17.25,-3.085) 3(-16.75,3.085) 4(-16.75,-3.085) 5(-16.25,3.085) 6(-16.25,-3.085) 7(-15.75,3.085) 8(-15.75,-3.085) 9(-15.25,3.085) 10(-15.25,-3.085) 11(-14.75,3.085) 12(-14.75,-3.085) 13(-14.25,3.085) 14(-14.25,-3.085) 15(-13.75,3.085) 16(-13.75,-3.085) 17(-13.25,3.085) 18(-13.25,-3.085) 19(-12.75,3.085) 20(-12.75,-3.085) 21(-12.25,3.085) 22(-12.25,-3.085) 23(-11.75,3.085) 24(-11.75,-3.085) 25(-11.25,3.085) 26(-11.25,-3.085) 27(-10.75,3.085) 28(-10.75,-3.085) 29(-10.25,3.085) 30(-10.25,-3.085) 31(-9.75,3.085) 32(-9.75,-3.085) 33(-9.25,3.085) 34(-9.25,-3.085) 35(-8.75,3.085) 36(-8.75,-3.085) 37(-8.25,3.085) 38(-8.25,-3.085) 39(-7.75,3.085) 40(-7.75,-3.085) 41(-7.25,3.085) 42(-7.25,-3.085) 43(-6.75,3.085) 44(-6.75,-3.085) 45(-6.25,3.085) 46(-6.25,-3.085) 47(-5.75,3.085) 48(-5.75,-3.085) 49(-5.25,3.085) 50(-5.25,-3.085) 51(-4.75,3.085) 52(-4.75,-3.085) 53(-4.25,3.085) 54(-4.25,-3.085) 55(-3.75,3.085) 56(-3.75,-3.085) 57(-3.25,3.085) 58(-3.25,-3.085) 59(-2.75,3.085) 60(-2.75,-3.085) 61(2.75,3.085) 62(2.75,-3.085) 63(3.25,3.085) 64(3.25,-3.085) 65(3.75,3.085) 66(3.75,-3.085) 67(4.25,3.085) 68(4.25,-3.085) 69(4.75,3.085) 70(4.75,-3.085) 71(5.25,3.085) 72(5.25,-3.085) 73(5.75,3.085) 74(5.75,-3.085) 75(6.25,3.085) 76(6.25,-3.085) 77(6.75,3.085) 78(6.75,-3.085) 79(7.25,3.085) 80(7.25,-3.085) 81(7.75,3.085) 82(7.75,-3.085) 83(8.25,3.085) 84(8.25,-3.085) 85(8.75,3.085) 86(8.75,-3.085) 87(9.25,3.085) 88(9.25,-3.085) 89(9.75,3.085) 90(9.75,-3.085) 91(10.25,3.085) 92(10.25,-3.085) 93(10.75,3.085) 94(10.75,-3.085) 95(11.25,3.085) 96(11.25,-3.085) 97(11.75,3.085) 98(11.75,-3.085) 99(12.25,3.085) 100(12.25,-3.085) 101(12.75,3.085) 102(12.75,-3.085) 103(13.25,3.085) 104(13.25,-3.085) 105(13.75,3.085) 106(13.75,-3.085) 107(14.25,3.085) 108(14.25,-3.085) 109(14.75,3.085) 110(14.75,-3.085) 111(15.25,3.085) 112(15.25,-3.085) 113(15.75,3.085) 114(15.75,-3.085) 115(16.25,3.085) 116(16.25,-3.085) 117(16.75,3.085) 118(16.75,-3.085) 119(17.25,3.085) 120(17.25,-3.085)
  rect 2.54x0.64 smd: G1(-18.445,0.005) G1(1.555,0.005) G4(-1.555,0.005) G4(18.445,0.005)
  rect 4.7x0.64 smd: G2(-13.175,0.005) G2(6.825,0.005) G3(-6.825,0.005) G3(13.175,0.005)
  silkscreen extent -20.16,-2.99 20.14,3.03
RES-4B [mil]
  rect 20x20 smd: 1(50,-27.5) 2(50,27.5) 3(17,-27.5) 4(17,27.5) 5(-17,-27.5) 6(-17,27.5) 7(-50,-27.5) 8(-50,27.5)
  silkscreen extent -70,-28 70,28
SAM(C816) [mm]
  rect 1.5x1.3 smd: 1(-12.3,-8.255) 2(-12.3,-5.715) 3(-12.3,-3.175) 4(-12.3,-0.635) 5(12.3,-8.255) 6(12.3,-5.715) 7(12.3,-3.175) 8(12.3,-0.635)
  rect 1.75x1 smd: 17(-5.5,4.445) 18(-5.5,6.985)
  round 2.2 hole 2.2 unplated: G0(-10.16,22.225) G0(10.16,-22.225)
  silkscreen extent -17.15,-29.59 14.61,26.42
SIP2 [mil]
  round 60 hole 40: 1(0,0) 2(100,0)
  silkscreen extent -50,-50 150,50
SIP3 [mil]
  rect 60x60 hole 40: 1(0,0)
  round 60 hole 40: 2(100,0) 3(200,0)
  silkscreen extent -50,-50 250,50
SMD214012 [mm]
  round 1.6 hole 1.6 unplated: 0(0,0) 0(8.23,0)
  rect 0.8x1.4 smd: 1(2.21,1.9) 1(2.21,-3.05) 2(3.48,1.9) 2(3.48,-3.05) 3(4.75,1.9) 3(4.75,-3.05) 4(6.02,1.9) 4(6.02,-3.05)
  rect 1.2x2.5 smd: G0(-0.3,2.55) G0(-0.3,-2.55) G0(8.53,-2.55) G0(8.53,2.55)
  silkscreen extent -1.3,-3.44 9.5,3.94
SO8 [mil]
  rect 20x60 smd: 1(0,0) 2(50,0) 3(100,0) 4(150,0) 5(150,225) 6(100,225) 7(50,225) 8(0,225)
  silkscreen extent -30,60 180,160
SO16 [mil]
  rect 25x75 smd: 1(0,0) 2(50,0) 3(100,0) 4(150,0) 5(200,0) 6(250,0) 7(300,0) 8(350,0) 9(350,235) 10(300,235) 11(250,235) 12(200,235) 13(150,235) 14(100,235) 15(50,235) 16(0,235)
  silkscreen extent -34,63 376,173
SO28 [mil]
  rect 75x25 smd: 1(0,0) 2(0,-50) 3(0,-100) 4(0,-150) 5(0,-200) 6(0,-250) 7(0,-300) 8(0,-350) 9(0,-400) 10(0,-450) 11(0,-500) 12(0,-550) 13(0,-600) 14(0,-650) 15(400,-650) 16(400,-600) 17(400,-550) 18(400,-500) 19(400,-450) 20(400,-400) 21(400,-350) 22(400,-300) 23(400,-250) 24(400,-200) 25(400,-150) 26(400,-100) 27(400,-50) 28(400,0)
  silkscreen extent 80,-685 320,35
SOD-123 [mm]
  rect 0.97x0.65 smd: 1(-1.74,0) 2(1.74,0)
  silkscreen extent -1.4,-0.8 1.4,0.8
SOT-23 [mil]
  rect 36x36 smd: 1(37.5,-40) 2(-37.5,-40)
  rect 36x50 smd: 3(0.5,40)
  silkscreen extent -58,-45 58,45
TAN-B [mil]
  rect 50x100 smd: 1(-60,0) 2(60,0)
  silkscreen extent -120,-75 110,75
TP [mil]
  round 60 hole 40: 1(0,0)
  silkscreen extent -45,-45 45,45
TSSOP8 [mm]
  rect 0.9x0.33 smd: 1(0,0) 2(0,-0.65) 3(0,-1.3) 4(0,-1.95) 5(4.5,-1.95) 6(4.5,-1.3) 7(4.5,-0.65) 8(4.5,0)
  silkscreen extent 0.89,-2.28 3.56,0.33
TSSOP14 [mm]
  rect 1x0.25 smd: 1(0,0) 2(0,-0.65) 3(0,-1.3) 4(0,-1.95) 5(0,-2.6) 6(0,-3.25) 7(0,-3.9) 8(6.4,-3.9) 9(6.4,-3.25) 10(6.4,-2.6) 11(6.4,-1.95) 12(6.4,-1.3) 13(6.4,-0.65) 14(6.4,0)
  silkscreen extent 0.94,-4.44 5.42,0.33
TSSOP16 [mm]
  rect 1.15x0.3 smd: 1(0,0) 2(0,-0.65) 3(0,-1.3) 4(0,-1.95) 5(0,-2.6) 6(0,-3.25) 7(0,-3.9) 8(0,-4.55) 9(6.4,-4.55) 10(6.4,-3.9) 11(6.4,-3.25) 12(6.4,-2.6) 13(6.4,-1.95) 14(6.4,-1.3) 15(6.4,-0.65) 16(6.4,0)
  silkscreen extent 0.94,-4.88 5.42,0.33
VB334 [mm]
  round 2 hole 1.3: 1(-3.125,3.125) 2(3.125,3.125) 3(3.125,-3.125) 4(-3.125,-3.125)
  round 2.032 hole 1.27: 5(0,0)
  silkscreen extent -5.5,-5.5 5.5,5.5
XTAL_socket [mil]
  round 80 hole 53: 1(100,0) 2(-100,0)
  silkscreen extent -215,-89 214,89

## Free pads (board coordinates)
  round 137.79 hole 137.79 unplated: 0(38375,50425) 0(42425,56775)
  round 137.8 hole 137.8 unplated: 0(38375,56775) 0(42425,50425)
  round 20 smd: 0(38575,50475) 0(39925,55025) 0(40800,54150) 0(41945,56450)

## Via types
v1: diameter 16, hole 8, TopLayer to BottomLayer, tented both sides, 568 vias
v2: diameter 16, hole 8, TopLayer to BottomLayer, 68 vias

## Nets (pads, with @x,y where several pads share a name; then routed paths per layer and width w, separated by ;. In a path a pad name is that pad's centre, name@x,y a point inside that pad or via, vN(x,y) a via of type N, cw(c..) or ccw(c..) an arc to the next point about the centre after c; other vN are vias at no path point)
+3V3: C9.1 C12.1 C66.2 CN1.48 CN9.4 CN10.28 R18.2 R34.2 R55.1 R57.2 TP1.1 TP3.1 U3.2 U11.1 | length 14821.6
  TopLayer w12: R55.1@38727.5,55200 v1(38775,55200) ; U3.2@39165,51900 U3.2@39185,51900 ; U3.2@39175,52373.82 C9.1@39175,52565 ; R18.2@39525,51102.5 v1(39525,51150) ; v1(39600,51000) R57.2@39600,51047.5 ; C66.2@39600,51277.5 39627.5,51277.5 v1(39650,51300) U11.1@39725,51300 ; CN9.4@39862.99,50953.35 v1(39862.99,51037.99) 39872.5,51047.5 C12.1@39872.5,51075 ; R34.2@40127.5,51150 v1(40175,51150)
  TopLayer w30: U3.2@39175,51910 U3.2@39175,52360 ; U3.2@39185,51900 v1(39425,51900) ; U3.2@39275,51850 v1(39425,51850)
  VCC w12: v1(38775,55200) 38775,55925 38950,56100 41550,56100 ; 40300,56100 CN10.28@40300,56625 ; CN1.48@41750,53400 41825,53475
  VCC w30: 39400,52575 39585,52760 40380,52760 40430,52810 40790,52810 40850,52750 41575,52750 41825,53000 41825,55825 41550,56100 ; v1(39425,51900) 39425,51525 v1(39650,51300) 39650,51120 ; v1(39525,51150) 39575,51100 ; 39600,51070 39630,51100 ; 39600,51085 v1(39600,51000) ; 39832.99,51100 39862.99,51070 39865,51070 39895,51100 ; v1(39862.99,51037.99) 39862.99,51097.01 ; v1(40175,51150) 40125,51100 39670,51100 ; 39575,51100 39600,51075 ; 39575,51100 39630,51100 ; 39575,51100 39670,51100 ; v1(39600,51000) 39600,51075 ; v1(39600,51000) 39600,51075 ; 39630,51100 39650,51120 ; 39650,51120 39670,51100
  VCC w50: v1(39175,52505) 39175,52525 39225,52575 39400,52575
  BottomLayer w12: v1(39175,52450) 39175,53125 TP1.1@39300,53250
  other v1: 39175,52475
+5V: C11.1 C13.2 C17.1 C24.2 C30.1 C45.1 C47.1 C49.1 C55.1 C57.1 C61.1 C62.1 C63.1 C64.2 C67.2 C75.2 CN4.1 CN10.25 CN16.1 CN16.2 CN17.1 JP2.2 JP3.2 JP3.4 R1.2 R3.2 R17.2 R22.2 R27.2 R28.1 R33.2 R36.1 R37.1 R38.1 R49.1 R50.2 R51.2 R52.2 R53.2 R67.2 R68.1 R69.1 R70.1 R71.1 R81.2 R82.1 R83.1 R84.1 R86.1 R87.1 R88.1 R89.1 R97.1 R100.2 R104.1 R107.1 RP1.2 RP1.4 RP1.6 RP1.8 RP2.2 RP2.4 RP2.6 RP2.8 RV1.3 RV4.1 TP2.1 U3.3 U6.6 U7.4 U10.3 U11.14 U12.8 U13.2 U14.7 U17.16 U18.16 U19.6 U19.21 U20.16 U21.14 U22.14 | length 21078.2
  TopLayer w12: U14.7@38425,56125.59 38474.41,56125.59 38525,56075 C57.1@38572.5,56075 38572.5,56050 v1(38597.5,56025) C55.1@38740,56025 ; R89.1@38627.5,56150 v1(38675,56150) ; R81.2@38627.5,56300 v1(38675,56300) ; R88.1@38627.5,56375 v1(38675,56375) ; v1(39000,51050) R28.1@39000,51097.5 ; U3.3@39075,52375 39075,52650 39225,52800 C11.1@39225,52880 ; v1(39150,55925) C24.2@39150,55972.5 ; v1(39151.77,51251.77) 39163.39,51263.39 U7.4@39163.39,51322.91 ; C24.2@39152.5,55975 U10.3@39250,55975 ; R22.2@39225,51652.5 v1(39225,51700) ; R17.2@39450,51102.5 v1(39450,51150) ; v1(39525,51525) R86.1@39572.5,51525 ; v1(39525,52075) R87.1@39572.5,52075 ; v1(39550,52425) U18.16@39550,52535 ; C45.1@39627.5,51925 C63.1@39627.5,51850 39725,51850 39750,51825 U19.6@39825,51825 ; C49.1@39627.5,53650 39627.5,53592.5 39645,53575 U20.16@39676.97,53575 ; C61.1@39660,51725 v1(39725,51725) ; R33.2@39677.5,56225 v1(39725,56225) ; v1(39697.5,52127.5) R71.1@39697.5,52200 ; v1(39797.5,52602.5) R97.1@39797.5,52650 ; U11.14@39976.97,51300 C67.2@40072.5,51300 ; v1(40150,52400) U17.16@40150,52535 ; U19.21@40225,51725 v1(40300,51725) ; v1(40297.5,52152.5) R70.1@40297.5,52200 ; R100.2@40300,50602.5 v1(40300,50680) ; v1(40300,51875) C62.1@40365,51875 ; v1(40330,52600) R68.1@40330,52650 ; v1(40350,51750) C47.1@40397.5,51750 ; U12.8@40425,53325 v1(40475,53325) ; v1(40447.5,52617.5) R69.1@40447.5,52650 ; R84.1@40452.5,51675 v1(40500,51675) ; R83.1@40452.5,52000 v1(40500,52000) ; R82.1@40452.5,52075 v1(40500,52075) ; R38.1@40602.5,53175 v1(40650,53175) ; R37.1@40602.5,53250 v1(40650,53250) ; R36.1@40602.5,53325 v1(40650,53325) ; R1.2@40675,51252.5 v1(40675,51300) ; R27.2@40700,51447.5 40747.5,51447.5 v1(40750,51450) ; R50.2@40750,51252.5 v1(40750,51295) ; U6.6@40751.18,51777.17 C13.2@40751.18,51923.68 ; v1(40800,51925) C17.1@40865,51925 ; R49.1@40825,51252.5 v1(40825,51300) ; C30.1@40852.5,52475 40852.5,52577.5 U13.2@40875,52600 ; R51.2@40900,51252.5 v1(40900,51300) ; R52.2@40975,51252.5 v1(40975,51300) ; v1(41020.28,52149.72) RV4.1@41020.28,52246.26 ; R53.2@41050,51252.5 v1(41050,51300) ; v1(41052.5,53352.5) RP1.2@41200,53352.5 ; v1(41200,51025) R3.2@41200,51072.5 ; v2(41275,52325) R104.1@41275,52372.5 ; v1(41325,53395) RP2.8@41325,53352.5 RP2.2@41425,53352.5 ; v1(41372.5,52152.5) R107.1@41372.5,52195 ; v1(41400,56250) R67.2@41400,56297.5 ; C75.2@41650,52227.5 41675,52227.5 41699.47,52251.97 U21.14@41750,52251.97 ; C64.2@41650,52627.5 41702.5,52627.5 41750,52675 U22.14@41750,52701.97 ; CN4.1@42254.92,53112.99 CN4.1@42449.8,53112.99
  TopLayer w30: C11.1@39305,52895 39305,52995 39360,53050 JP3.2@39450,53050
  VCC w12: v1(38500.57,56099.43) 38549.43,56099.43 38575,56125 38575,56650 38850,56925 ; 38575,56300 v1(38675,56300) ; 38575,56375 v1(38675,56375) ; v1(39000,51050) 39000,51125 39425,51125 v1(39450,51150) ; 39100,51125 39100,51200 v1(39151.77,51251.77) 39151.77,51451.77 39225,51525 39225,52125 39425,52325 ; 39200,55925 v1(39150,55925) 39150,55700 39300,55550 39300,54725 JP2.2@39425,54600 39375,54550 39375,53125 JP3.2@39450,53050 ; 39375,53600 39750,53600 39875,53475 41325,53475 v1(41325,53395) ; v1(39525,51525) 39700,51700 39700,52325 ; v1(39525,52075) 39700,52075 ; 39550,52325 v1(39550,52425) ; TP2.1@39550,53250 39550,53600 ; 39700,51725 v1(39725,51725) ; 39797.5,52327.5 v1(39797.5,52602.5) ; v1(40025,51300) 40025,52325 ; 40150,52325 v1(40150,52400) ; v1(40297.5,52152.5) 40300,52150 40325,52150 ; v1(40300,51725) 40325,51750 40425,51750 v1(40500,51675) ; 40325,52325 40325,52595 v1(40330,52600) ; v1(40447.5,52617.5) 40475,52590 40475,52325 ; v1(40475,53325) 40475,53475 ; v1(40500,52000) 40500,52325 ; v1(40650,53175) 40650,53475 ; v1(40675,51300) 41100,51300 41200,51200 v1(41200,51025) ; v1(40750,51295) v1@40750,51823.82 ; 40875,52325 U13.2@40875,52600 ; v1(41020.28,52149.72) 41020.28,52324.72 ; 41050,53475 41050,53355 v1(41052.5,53352.5) ; 41250,52300 41250,52325 ; 41430,52220 41545,52220 41600,52275 41688.94,52275 v2(41711.97,52251.97) ; 42237.01,53112.99 v1(42350,53112.99) ; 42325,51775 CN16.2@42325,51900 42605,51900 ; 42425,51770 CN16.1@42425,51900
  VCC w30: JP3.4@39550,53050 TP2.1@39550,53250
  BottomLayer w12: v1(39075,52450) v1(39075,52525)
  other v1: 40751.18,51825 39700,51850 39075,52475 39075,52500 39627.5,53600
  other v2: 41724.91,52649.91
+5V_MCU: C71.1 C72.1 C73.1 CN2.7 CN2.8 CN2.49 JP2.1 L1.1 U1.7 U1.8 U1.49 | length 5186.1
  TopLayer w7: C71.1@39727.5,54550 v1(39775,54550) 39888.98,54663.98 U1.8@40042.91,54663.98 ; C72.1@39727.5,54625 39800,54625 39864.57,54689.57 40135.43,54689.57 v1(40150,54675) ; CN2.8@39779.92,55578.54 v1@39779.92,55639.92 ; v1@39779.92,55750.08 CN2.7@39779.92,55821.46 ; v1(40193.31,55771.69) CN2.49@40193.31,55821.46 ; U1.49@40657.09,54561.61 40913.39,54561.61 40922.5,54552.5 C73.1@40975,54552.5
  TopLayer w12: L1.1@40575,53900 40625,53900 v1(40635,53900)
  VCC w7: JP2.1@39525,54600 39925,54600 40000,54675 v1(40150,54675) 40175,54650 40436.61,54650 40525,54561.61 ; v1(39780,55640) v1(39780,55750) 39801.69,55771.69 40228.31,55771.69 40300,55700 40300,54650 ; 40575,53900 40575,54150 40525,54200 40525,54561.61 ; 40850,54561.61 40525,54561.61
  other v1: 40610,53900 40825,54560 39775,54625
+5V_VDDA: C7.1 C10.1 CN2.23 L1.2 R74.2 U1.23 | length 4872.3
  TopLayer w7: CN2.23@39937.4,55821.46 v1(39937.4,55885) ; R74.2@40010,54125 40035,54125 40158.07,54248.07 U1.23@40158.07,54292.91
  TopLayer w12: C10.1@40325,53952.5 40352.5,53952.5 v1(40385,53985) 40515,53985 40547.5,53952.5 L1.2@40575,53952.5
  VCC w7: 40400,54050 40400,53925 40475,53850 40680,53850
  VCC w12: 39925,55897.4 v1(39937.4,55885)
  VCC w20: 39925,55897.4 39925,55950 39975,56000 40750,56000 41075,55675 41075,54900 40975,54800 40975,54050 40775,53850 40535,53850 ; 40175,54200 40250,54200 40400,54050
  other v1: 40360,53960 40125,54215 40149.87,54239.87
D5V: CN1.49 CN5.19 JP3.1 | length 4846.6
  VCC w20: CN5.19@38950,54800 38850,54700 38850,53100 39000,52950 JP3.1@39450,52950 39500,53000 41350,53000 ; 39615,53035 39640,53035 39705,53100 39790,53100 39855,53035 ; 39655,52950 39705,52900 39785,52900 39840,52955
E5V: C8.1 JP3.3 U4.3 | length 1572.9
  TopLayer w20: U4.3@38351.57,51848.43 38428.15,51925 C8.1@38820,51925
  VCC w20: U4.3@38351.57,51848.43 38625,52121.85 38625,52175
  VCC w45: 39425,52830 JP3.3@39550,52955
  VCC w50: 39165,52715 39282.5,52832.5 ; 39285,52830 39425,52830 ; 39305,52865 39450,52865 ; JP3.3@39550,52950 JP3.3@39550,52955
